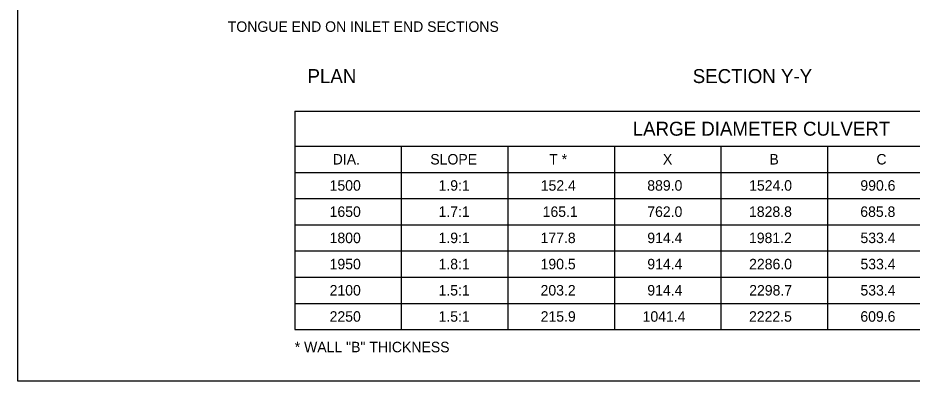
# Model space of a CAD drawing. Extents: x 49991.4 to 50022.1, y 49985 to 50011.4.
# Drawn here: x 49999.38 to 50004.5, y 49987.8 to 49989.88 of the extents above; entities that cross this region are included whole.
import ezdxf

# ---------------------------------------------------------------- set-up
doc = ezdxf.new("R2010")
doc.units = 0
doc.layers.add('Level 1', color=7, linetype='Continuous')
doc.layers.add('Level 2', color=7, linetype='Continuous')

msp = doc.modelspace()

# ---------------------------------------------------------------- linework, layer by layer
at = {"layer": 'Level 1'}
msp.add_lwpolyline([(49999.3835, 49998.9992), (50016.7501, 49998.9992), (50016.7501, 49987.7988), (49999.3835, 49987.7988)], close=True, dxfattribs=at)
at = {"layer": 'Level 2'}
for p, q in [((50000.968, 49989.3439), (50000.968, 49988.0939)), ((50000.968, 49989.3439), (50006.458, 49989.3439)), ((50000.968, 49989.1439), (50000.968, 49988.9939)), ((50000.968, 49989.1439), (50006.458, 49989.1439)), ((50001.578, 49989.1439), (50001.578, 49988.0939)), ((50002.188, 49989.1439), (50002.188, 49988.0939)), ((50002.798, 49989.1439), (50002.798, 49988.0939)), ((50003.408, 49989.1439), (50003.408, 49988.0939)), ((50004.018, 49989.1439), (50004.018, 49988.0939)), ((50000.968, 49988.9939), (50006.458, 49988.9939)), ((50000.968, 49988.8439), (50006.458, 49988.8439)), ((50000.968, 49988.6939), (50006.458, 49988.6939)), ((50000.968, 49988.5439), (50006.458, 49988.5439)), ((50000.968, 49988.3939), (50006.458, 49988.3939)), ((50000.968, 49988.2439), (50006.458, 49988.2439)), ((50000.968, 49988.0939), (50006.458, 49988.0939))]:
    msp.add_line(p, q, dxfattribs=at)

# ---------------------------------------------------------------- texts
for s, height, p in [('TONGUE END ON INLET END SECTIONS', 0.06, (50000.585, 49989.7983)), ('PLAN', 0.08, (50001.0412, 49989.505)), ('SECTION Y-Y', 0.08, (50003.2462, 49989.505)), ('LARGE DIAMETER CULVERT', 0.08, (50002.9027, 49989.2039)), ('DIA.', 0.06, (50001.1856, 49989.0389)), ('SLOPE', 0.06, (50001.7442, 49989.0389)), ('T *', 0.06, (50002.4248, 49989.0389)), ('X', 0.06, (50003.0756, 49989.0389)), ('B', 0.06, (50003.6853, 49989.0389)), ('C', 0.06, (50004.2976, 49989.0389)), ('1500', 0.06, (50001.1679, 49988.8889)), ('1.9:1', 0.06, (50001.7914, 49988.8889)), ('152.4', 0.06, (50002.3764, 49988.8889)), ('889.0', 0.06, (50002.9861, 49988.8889)), ('1524.0', 0.06, (50003.5692, 49988.8889)), ('990.6', 0.06, (50004.2059, 49988.8889)), ('1650', 0.06, (50001.1679, 49988.7389)), ('1.7:1', 0.06, (50001.7914, 49988.7389)), ('165.1', 0.06, (50002.3874, 49988.7389)), ('762.0', 0.06, (50002.9861, 49988.7389)), ('1828.8', 0.06, (50003.5685, 49988.7389)), ('685.8', 0.06, (50004.2054, 49988.7389)), ('1800', 0.06, (50001.1679, 49988.5889)), ('1.9:1', 0.06, (50001.7914, 49988.5889)), ('177.8', 0.06, (50002.3754, 49988.5889)), ('914.4', 0.06, (50002.9864, 49988.5889)), ('1981.2', 0.06, (50003.5683, 49988.5889)), ('533.4', 0.06, (50004.2064, 49988.5889)), ('1950', 0.06, (50001.1679, 49988.4389)), ('1.8:1', 0.06, (50001.7914, 49988.4389)), ('190.5', 0.06, (50002.3755, 49988.4389)), ('914.4', 0.06, (50002.9864, 49988.4389)), ('2286.0', 0.06, (50003.5691, 49988.4389)), ('533.4', 0.06, (50004.2064, 49988.4389)), ('2100', 0.06, (50001.1679, 49988.2889)), ('1.5:1', 0.06, (50001.7914, 49988.2889)), ('203.2', 0.06, (50002.3753, 49988.2889)), ('914.4', 0.06, (50002.9864, 49988.2889)), ('2298.7', 0.06, (50003.5696, 49988.2889)), ('533.4', 0.06, (50004.2064, 49988.2889)), ('2250', 0.06, (50001.1679, 49988.1389)), ('1.5:1', 0.06, (50001.7914, 49988.1389)), ('215.9', 0.06, (50002.3759, 49988.1389)), ('1041.4', 0.06, (50002.9595, 49988.1389)), ('2222.5', 0.06, (50003.5685, 49988.1389)), ('609.6', 0.06, (50004.2059, 49988.1389)), ('* WALL "B" THICKNESS', 0.06, (50000.968, 49987.9639))]:
    msp.add_text(s, height=height, dxfattribs=at).set_placement(p)

doc.saveas('drawing.dxf')
